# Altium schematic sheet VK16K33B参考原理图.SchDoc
size A3
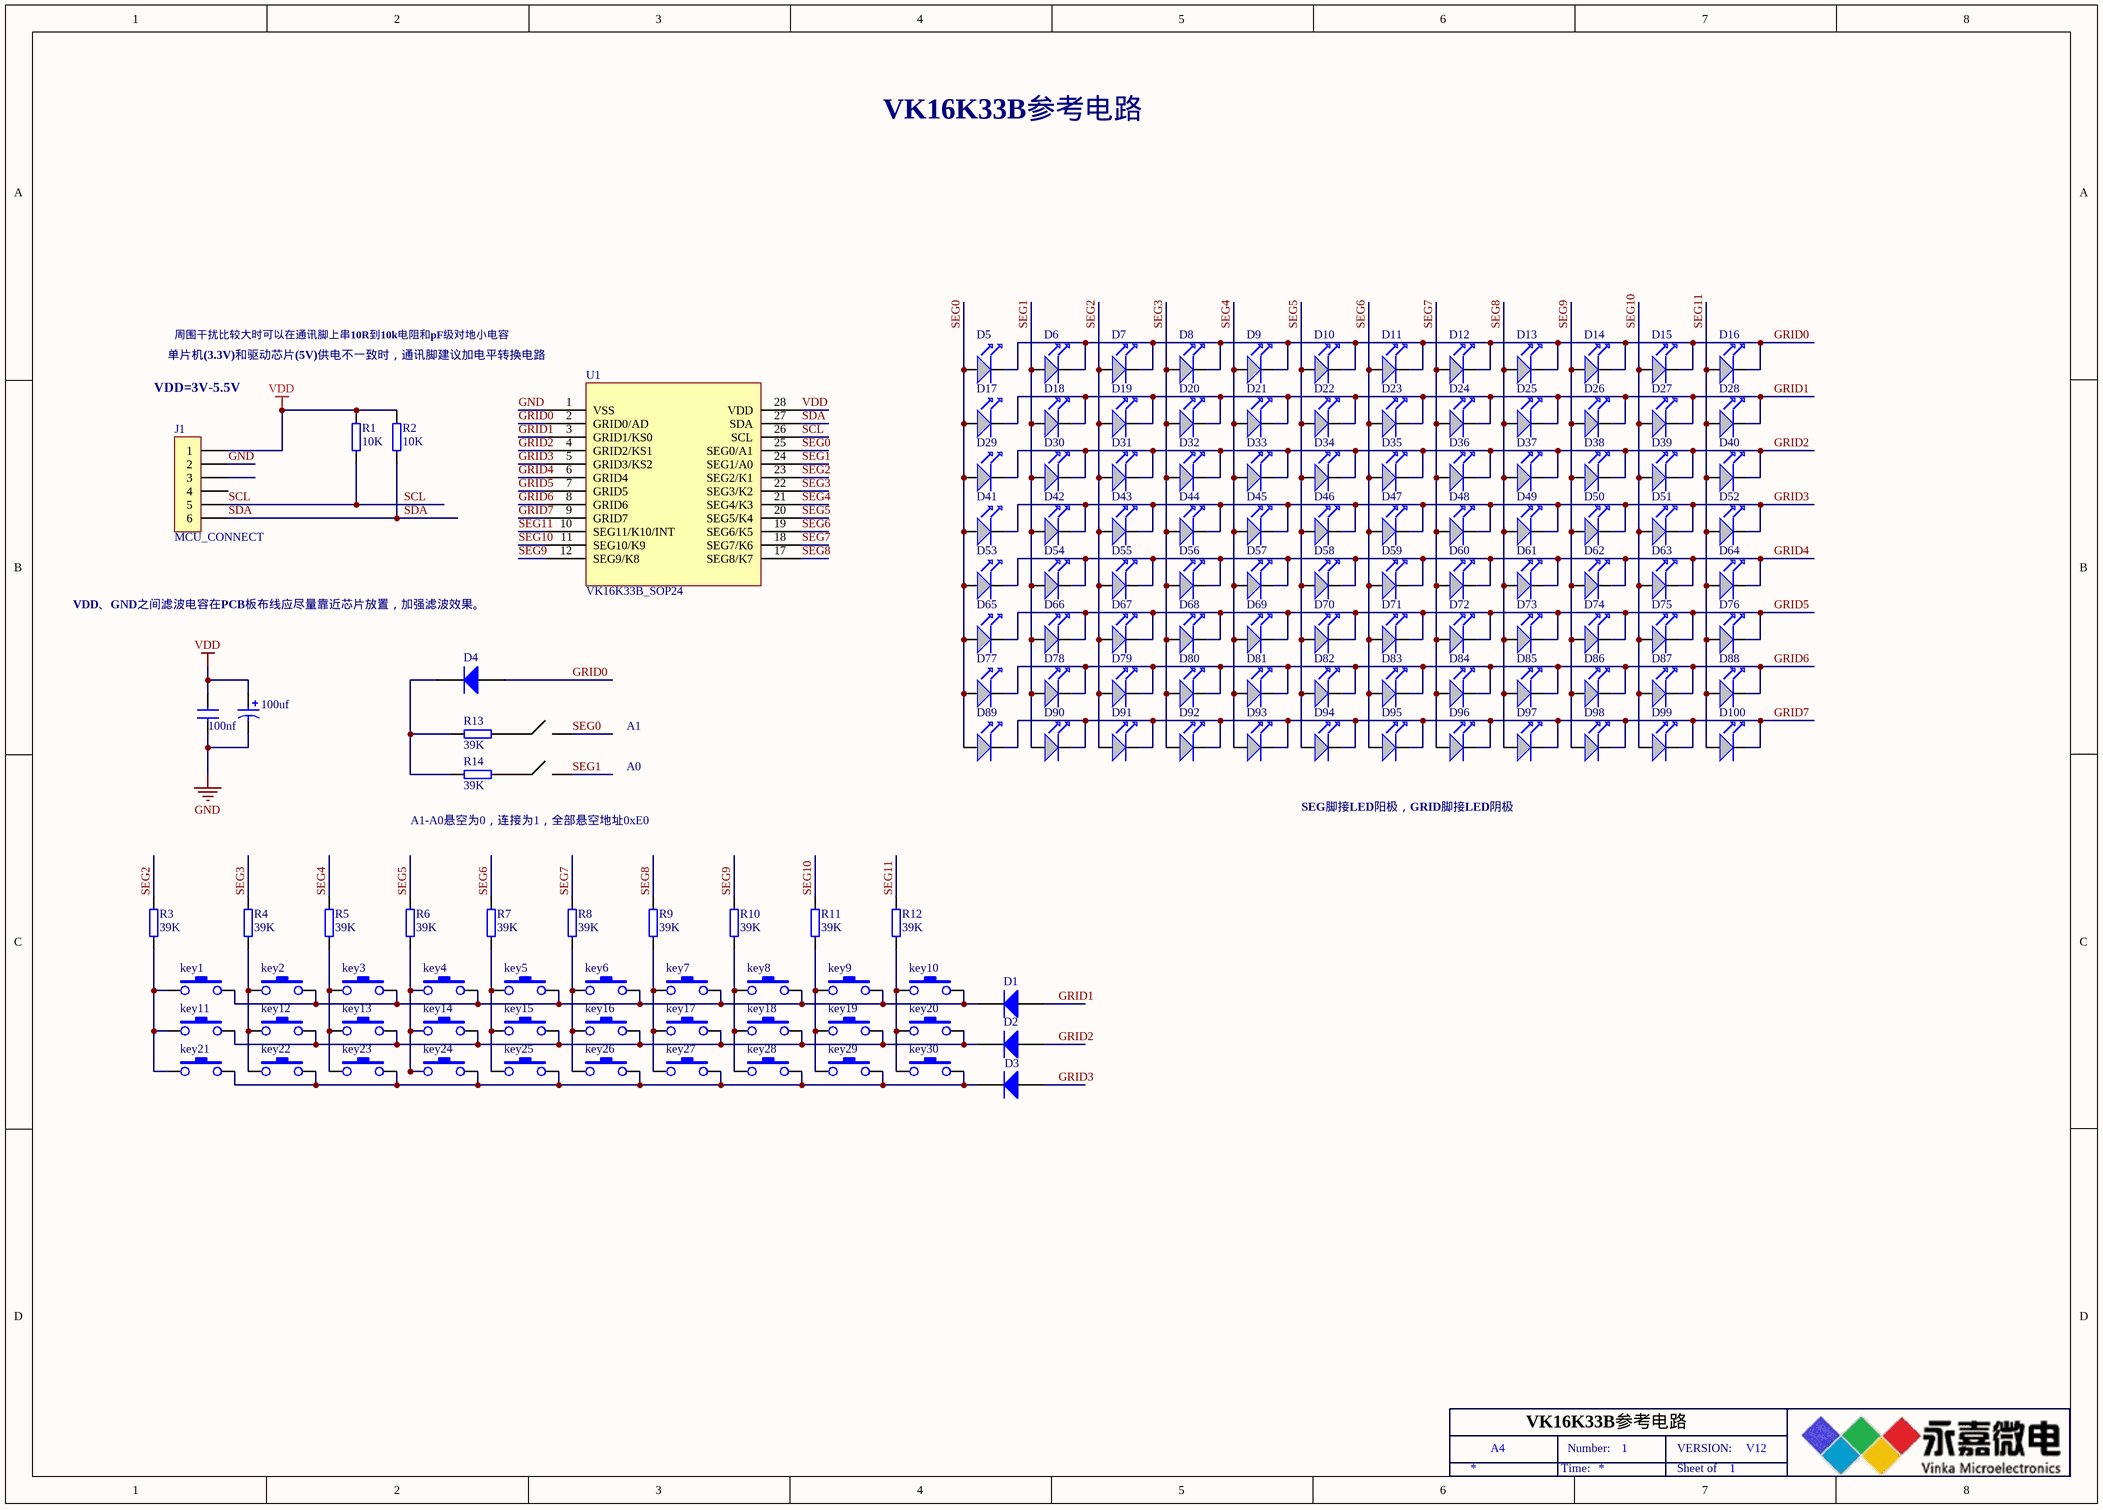
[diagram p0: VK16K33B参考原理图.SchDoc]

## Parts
1  01  (value not drawn)
2  02  (value not drawn)
100nf  CAP  (value not drawn)
100uf  CAP2  (value not drawn)
D1  Diode 1N4003  [DO-41]  (value not drawn)
D2  (no value)  [DO-41]
D3  (no value)  [DO-41]
D4  Diode 1N4003  [DO-41]  (value not drawn)
D5  (no value)  [1206-LED]
D6  (no value)  [1206-LED]
D7  (no value)  [1206-LED]
D8  (no value)  [1206-LED]
D9  (no value)  [1206-LED]
D10  (no value)  [1206-LED]
D11  (no value)  [1206-LED]
D12  (no value)  [1206-LED]
D13  (no value)  [1206-LED]
D14  (no value)  [1206-LED]
D15  (no value)  [1206-LED]
D16  (no value)  [1206-LED]
D17  (no value)  [1206-LED]
D18  (no value)  [1206-LED]
D19  (no value)  [1206-LED]
D20  (no value)  [1206-LED]
D21  (no value)  [1206-LED]
D22  (no value)  [1206-LED]
D23  (no value)  [1206-LED]
D24  (no value)  [1206-LED]
D25  (no value)  [1206-LED]
D26  (no value)  [1206-LED]
D27  (no value)  [1206-LED]
D28  (no value)  [1206-LED]
D29  (no value)  [1206-LED]
D30  (no value)  [1206-LED]
D31  (no value)  [1206-LED]
D32  (no value)  [1206-LED]
D33  (no value)  [1206-LED]
D34  (no value)  [1206-LED]
D35  (no value)  [1206-LED]
D36  (no value)  [1206-LED]
D37  (no value)  [1206-LED]
D38  (no value)  [1206-LED]
D39  (no value)  [1206-LED]
D40  (no value)  [1206-LED]
D41  (no value)  [1206-LED]
D42  (no value)  [1206-LED]
D43  (no value)  [1206-LED]
D44  (no value)  [1206-LED]
D45  (no value)  [1206-LED]
D46  (no value)  [1206-LED]
D47  (no value)  [1206-LED]
D48  (no value)  [1206-LED]
D49  (no value)  [1206-LED]
D50  (no value)  [1206-LED]
D51  (no value)  [1206-LED]
D52  (no value)  [1206-LED]
D53  (no value)  [1206-LED]
D54  (no value)  [1206-LED]
D55  (no value)  [1206-LED]
D56  (no value)  [1206-LED]
D57  (no value)  [1206-LED]
D58  (no value)  [1206-LED]
D59  (no value)  [1206-LED]
D60  (no value)  [1206-LED]
D61  (no value)  [1206-LED]
D62  (no value)  [1206-LED]
D63  (no value)  [1206-LED]
D64  (no value)  [1206-LED]
D65  (no value)  [1206-LED]
D66  (no value)  [1206-LED]
D67  (no value)  [1206-LED]
D68  (no value)  [1206-LED]
D69  (no value)  [1206-LED]
D70  (no value)  [1206-LED]
D71  (no value)  [1206-LED]
D72  (no value)  [1206-LED]
D73  (no value)  [1206-LED]
D74  (no value)  [1206-LED]
D75  (no value)  [1206-LED]
D76  (no value)  [1206-LED]
D77  (no value)  [1206-LED]
D78  (no value)  [1206-LED]
D79  (no value)  [1206-LED]
D80  (no value)  [1206-LED]
D81  (no value)  [1206-LED]
D82  (no value)  [1206-LED]
D83  (no value)  [1206-LED]
D84  (no value)  [1206-LED]
D85  (no value)  [1206-LED]
D86  (no value)  [1206-LED]
D87  (no value)  [1206-LED]
D88  (no value)  [1206-LED]
D89  (no value)  [1206-LED]
D90  (no value)  [1206-LED]
D91  (no value)  [1206-LED]
D92  (no value)  [1206-LED]
D93  (no value)  [1206-LED]
D94  (no value)  [1206-LED]
D95  (no value)  [1206-LED]
D96  (no value)  [1206-LED]
D97  (no value)  [1206-LED]
D98  (no value)  [1206-LED]
D99  (no value)  [1206-LED]
D100  (no value)  [1206-LED]
J1  MCU_CONNECT
key1  (no value)  [AN12]
key2  (no value)  [AN12]
key3  (no value)  [AN12]
key4  (no value)  [AN12]
key5  (no value)  [AN12]
key6  (no value)  [AN12]
key7  (no value)  [AN12]
key8  (no value)  [AN12]
key9  (no value)  [AN12]
key10  (no value)  [AN12]
key11  (no value)  [AN12]
key12  (no value)  [AN12]
key13  (no value)  [AN12]
key14  (no value)  [AN12]
key15  (no value)  [AN12]
key16  (no value)  [AN12]
key17  (no value)  [AN12]
key18  (no value)  [AN12]
key19  (no value)  [AN12]
key20  (no value)  [AN12]
key21  (no value)  [AN12]
key22  (no value)  [AN12]
key23  (no value)  [AN12]
key24  (no value)  [AN12]
key25  (no value)  [AN12]
key26  (no value)  [AN12]
key27  (no value)  [AN12]
key28  (no value)  [AN12]
key29  (no value)  [AN12]
key30  (no value)  [AN12]
R1  10K  [0603-R]
R2  10K  [0603-R]
R3  39K  [0603-R]
R4  39K  [0603-R]
R5  39K  [0603-R]
R6  39K  [0603-R]
R7  39K  [0603-R]
R8  39K  [0603-R]
R9  39K  [0603-R]
R10  39K  [0603-R]
R11  39K  [0603-R]
R12  39K  [0603-R]
R13  39K  [0603-R]
R14  39K  [0603-R]
U1  VK16K33B_SOP24

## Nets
GND: 100nf.2 100uf.2 J1.2 U1.1(VSS)
VDD: 100nf.1 100uf.1 J1.1 R1.1 R2.1 U1.28(VDD)
GRID0: D4.1(A) D5.2 D6.2 D7.2 D8.2 D9.2 D10.2 D11.2 D12.2 D13.2 D14.2 D15.2 D16.2 U1.2(GRID0/AD)
GRID1: D1.1(A) D17.2 D18.2 D19.2 D20.2 D21.2 D22.2 D23.2 D24.2 D25.2 D26.2 D27.2 D28.2 U1.3(GRID1/KS0)
GRID2: D2.1(A) D29.2 D30.2 D31.2 D32.2 D33.2 D34.2 D35.2 D36.2 D37.2 D38.2 D39.2 D40.2 U1.4(GRID2/KS1)
GRID3: D3.1(A) D41.2 D42.2 D43.2 D44.2 D45.2 D46.2 D47.2 D48.2 D49.2 D50.2 D51.2 D52.2 U1.5(GRID3/KS2)
GRID4: D53.2 D54.2 D55.2 D56.2 D57.2 D58.2 D59.2 D60.2 D61.2 D62.2 D63.2 D64.2 U1.6(GRID4)
GRID5: D65.2 D66.2 D67.2 D68.2 D69.2 D70.2 D71.2 D72.2 D73.2 D74.2 D75.2 D76.2 U1.7(GRID5)
GRID6: D77.2 D78.2 D79.2 D80.2 D81.2 D82.2 D83.2 D84.2 D85.2 D86.2 D87.2 D88.2 U1.8(GRID6)
GRID7: D89.2 D90.2 D91.2 D92.2 D93.2 D94.2 D95.2 D96.2 D97.2 D98.2 D99.2 D100.2 U1.9(GRID7)
SCL: J1.5 R1.2 U1.26(SCL)
SDA: J1.6 R2.2 U1.27(SDA)
SEG0: D5.1 D17.1 D29.1 D41.1 D53.1 D65.1 D77.1 D89.1 U1.25(SEG0/A1)
SEG1: D6.1 D18.1 D30.1 D42.1 D54.1 D66.1 D78.1 D90.1 U1.24(SEG1/A0)
SEG2: D7.1 D19.1 D31.1 D43.1 D55.1 D67.1 D79.1 D91.1 R3.1 U1.23(SEG2/K1)
SEG3: D8.1 D20.1 D32.1 D44.1 D56.1 D68.1 D80.1 D92.1 R4.1 U1.22(SEG3/K2)
SEG4: D9.1 D21.1 D33.1 D45.1 D57.1 D69.1 D81.1 D93.1 R5.1 U1.21(SEG4/K3)
SEG5: D10.1 D22.1 D34.1 D46.1 D58.1 D70.1 D82.1 D94.1 R6.1 U1.20(SEG5/K4)
SEG6: D11.1 D23.1 D35.1 D47.1 D59.1 D71.1 D83.1 D95.1 R7.1 U1.19(SEG6/K5)
SEG7: D12.1 D24.1 D36.1 D48.1 D60.1 D72.1 D84.1 D96.1 R8.1 U1.18(SEG7/K6)
SEG8: D13.1 D25.1 D37.1 D49.1 D61.1 D73.1 D85.1 D97.1 R9.1 U1.17(SEG8/K7)
SEG9: D14.1 D26.1 D38.1 D50.1 D62.1 D74.1 D86.1 D98.1 R10.1 U1.12(SEG9/K8)
SEG10: D15.1 D27.1 D39.1 D51.1 D63.1 D75.1 D87.1 D99.1 R11.1 U1.11(SEG10/K9)
SEG11: D16.1 D28.1 D40.1 D52.1 D64.1 D76.1 D88.1 D100.1 R12.1 U1.10(SEG11/K10/INT)
NetD1_2: D1.2(K) key1.2 key2.2 key3.2 key4.2 key5.2 key6.2 key7.2 key8.2 key9.2 key10.2
NetD2_2: D2.2(K) key11.2 key12.2 key13.2 key14.2 key15.2 key16.2 key17.2 key18.2 key19.2 key20.2
NetD3_2: D3.2(K) key21.2 key22.2 key23.2 key24.2 key25.2 key26.2 key27.2 key28.2 key29.2 key30.2
NetD4_2: D4.2(K) R13.1 R14.1
Netkey1_1: key1.1 key11.1 key21.1 R3.2
Netkey2_1: key2.1 key12.1 key22.1 R4.2
Netkey3_1: key3.1 key13.1 key23.1 R5.2
Netkey4_1: key4.1 key14.1 key24.1 R6.2
Netkey5_1: key5.1 key15.1 key25.1 R7.2
Netkey6_1: key6.1 key16.1 key26.1 R8.2
Netkey7_1: key7.1 key17.1 key27.1 R9.2
Netkey8_1: key8.1 key18.1 key28.1 R10.2
Netkey9_1: key9.1 key19.1 key29.1 R11.2
Netkey10_1: key10.1 key20.1 key30.1 R12.2

Not connected (* = marked no-connect by the designer): J1 3 4; R13 2; R14 2

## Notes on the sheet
- VK16K33B参考电路
- 单片机(3.3V)和驱动芯片(5V)供电不一致时，通讯脚建议加电平转换电路
- 周围干扰比较大时可以在通讯脚上串10R到10k电阻和pF级对地小电容
- VDD=3V-5.5V
- VDD、GND之间滤波电容在PCB板布线应尽量靠近芯片放置，加强滤波效果。
- A0
- A1
- (near R14) A1-A0悬空为0，连接为1，全部悬空地址0xE0
- SEG脚接LED阳极，GRID脚接LED阴极
- A4
- Number:
- 1
- VERSION:
- V12
- Time:
- Sheet of

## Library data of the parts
1 2 = Component_1
100nf = CAP: Capacitor
100uf = CAP2: Bi-Polar Capacitor
D1-D4 = Diode 1N4003: 1 Amp General Purpose Rectifier
D5-D100 = LED: Text Field1: 30; Text Field2: 20
J1 = CON6: Connector
key1-key30 = KEY
R1-R14 = RES: Resistor
U1 = VK16K33B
